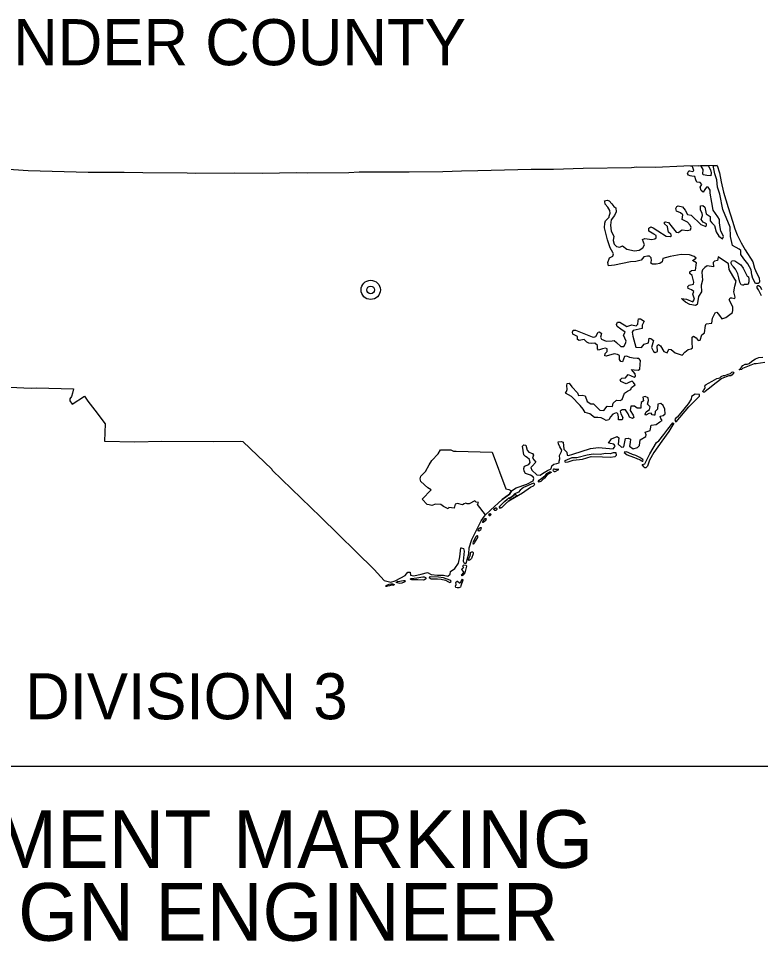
# Model space of a CAD drawing. Extents: x -63 to 3072, y 0 to 1100.
# Drawn here: x 1596 to 1653.9, y 945.4 to 1017.5 of the extents above; entities that cross this region are included whole.
import ezdxf

# ---------------------------------------------------------------- set-up
doc = ezdxf.new("R2010")
doc.units = 0
doc.layers.add('Level 15', color=7, linetype='Continuous')
doc.layers.add('Sheet_Plan_CELL', color=7, linetype='Continuous')

msp = doc.modelspace()

# ---------------------------------------------------------------- linework, layer by layer
at = {"layer": 'Level 15'}
for points in [[(1631.909, 979.673), (1631.735, 979.69), (1631.618, 979.805), (1631.178, 979.557), (1631.014, 979.558), (1630.928, 979.613), (1630.8, 979.581), (1630.649, 979.499), (1630.258, 979.606), (1630.083, 979.542), (1630.014, 979.23), (1629.599, 979.274), (1629.543, 979.189), (1629.177, 979.359), (1628.961, 979.53), (1628.554, 979.545), (1628.263, 979.446), (1628.064, 979.48), (1627.894, 979.522), (1627.502, 979.938), (1628.202, 980.67), (1627.955, 980.82), (1627.422, 981.301), (1627.363, 981.513), (1627.412, 981.721), (1627.762, 982.081), (1628.046, 982.615), (1628.254, 982.945), (1628.758, 983.482), (1628.946, 983.775), (1629.402, 983.792), (1629.758, 983.786), (1629.946, 983.686), (1630.177, 983.674), (1632.98, 983.611), (1634.041, 980.734), (1634.264, 980.682), (1634.491, 980.574), (1634.324, 980.333), (1633.758, 979.919), (1632.842, 979.08), (1632.45, 978.717), (1631.828, 979.525)], [(1634.702, 980.071), (1634.284, 979.814), (1634.023, 979.561), (1633.714, 979.272), (1633.568, 979.235), (1633.532, 979.285), (1633.547, 979.361), (1633.624, 979.445), (1633.945, 979.752), (1634.147, 979.903), (1634.17, 979.936), (1634.242, 980.01), (1634.358, 980.021), (1634.645, 980.219), (1634.729, 980.344), (1634.911, 980.192)], [(1633.123, 979.177), (1633.244, 979.256), (1633.283, 979.262), (1633.333, 979.211), (1633.341, 979.178), (1633.326, 979.13), (1633.29, 979.086), (1633.254, 979.06), (1633.224, 979.05), (1633.19, 979.046), (1633.152, 979.081), (1633.115, 979.13)], [(1632.863, 978.708), (1632.76, 978.653), (1632.722, 978.718), (1632.776, 978.778)]]:
    msp.add_lwpolyline(points, close=True, dxfattribs=at)
for radius in [0.752, 0.3]:
    msp.add_circle((1623.5, 996.27), radius, dxfattribs=at)
at = {"layer": 'Sheet_Plan_CELL'}
msp.add_line((1662.022, 959.06), (1562.024, 959.06), dxfattribs=at)
for points in [[(1650.508, 1005.987), (1647.919, 1005.917), (1645.716, 1005.833), (1644.265, 1005.84), (1643.848, 1005.793), (1640.061, 1005.739), (1637.767, 1005.667), (1636.007, 1005.661), (1631.854, 1005.569), (1630.568, 1005.527), (1629.128, 1005.496), (1626.496, 1005.468), (1625.258, 1005.452), (1622.589, 1005.446), (1621.795, 1005.395), (1618.594, 1005.382), (1617.714, 1005.41), (1615.069, 1005.352), (1612.887, 1005.382), (1609.813, 1005.346), (1609.189, 1005.384), (1605.718, 1005.394), (1604.28, 1005.421), (1601.974, 1005.443), (1601.468, 1005.431), (1596.787, 1005.562), (1594.085, 1005.742)], [(1649.267, 1004.036), (1649.193, 1004.3), (1649.328, 1004.483), (1649.191, 1004.647), (1648.941, 1004.667), (1648.853, 1004.864), (1648.779, 1005.128), (1648.556, 1005.143), (1648.42, 1005.169), (1648.292, 1005.235), (1648.218, 1005.36), (1648.298, 1005.553), (1648.399, 1005.562), (1648.614, 1005.507), (1648.703, 1005.601), (1648.62, 1005.825), (1648.557, 1005.934), (1648.429, 1005.931)], [(1649.1, 1005.948), (1649.812, 1005.966), (1649.998, 1005.652), (1650.052, 1005.412), (1650.034, 1005.171), (1649.705, 1005.205), (1649.466, 1005.251), (1649.404, 1005.306), (1649.416, 1005.663), (1649.277, 1005.919), (1649.1, 1005.948)], [(1650.508, 1005.987), (1650.701, 1005.419), (1650.819, 1004.693), (1651.009, 1003.896), (1651.383, 1002.706), (1651.722, 1001.638), (1651.905, 1001.03), (1652.087, 1000.566), (1652.385, 999.951), (1652.709, 999.402), (1653.288, 998.461), (1653.433, 997.962), (1653.589, 997.589), (1653.79, 997.222), (1653.823, 996.898), (1653.783, 996.828), (1653.704, 996.761), (1653.612, 996.758), (1653.518, 996.765), (1653.3, 997.161), (1653.225, 997.433), (1653.16, 997.83), (1652.906, 998.293), (1652.593, 998.683), (1652.358, 999.028), (1652.352, 999.357), (1652.227, 999.453), (1651.718, 999.738), (1651.552, 1000.427), (1651.538, 1001.159), (1650.972, 1002.542), (1650.718, 1003.751), (1650.534, 1004.289), (1650.504, 1004.868), (1650.331, 1005.318), (1650.2, 1005.976), (1650.508, 1005.987)], [(1642.456, 1002.782), (1642.62, 1002.682), (1642.646, 1002.374), (1642.519, 1002.079), (1642.256, 1001.727), (1642.194, 1001.324), (1642.259, 1000.856), (1642.464, 1000.46), (1642.414, 1000.125), (1642.499, 999.833), (1642.674, 999.649), (1642.917, 999.605), (1643.135, 999.716), (1643.475, 999.446), (1644.078, 999.307), (1644.441, 999.377), (1644.712, 999.547), (1644.858, 999.796), (1644.77, 999.992), (1644.687, 1000.214), (1644.869, 1000.29), (1645.413, 1000.203), (1645.647, 1000.255), (1645.76, 1000.331), (1645.767, 1000.509), (1645.59, 1000.611), (1645.191, 1000.865), (1645.191, 1001.086), (1645.336, 1001.183), (1645.534, 1001.119), (1645.896, 1000.885), (1646.545, 1000.473), (1646.858, 1000.428), (1646.96, 1000.519), (1646.911, 1000.625), (1646.729, 1000.77), (1646.681, 1001.027), (1646.647, 1001.213), (1646.423, 1001.435), (1646.403, 1001.549), (1646.481, 1001.59), (1646.72, 1001.517), (1647.004, 1001.173), (1647.334, 1000.78), (1647.509, 1000.746), (1647.649, 1000.886), (1647.789, 1000.956), (1648.186, 1000.908), (1648.435, 1000.957), (1648.485, 1001.141), (1648.424, 1001.332), (1648.215, 1001.552), (1647.778, 1001.759), (1647.849, 1002.119), (1647.669, 1002.278), (1647.36, 1002.42), (1647.288, 1002.627), (1647.376, 1002.79), (1647.481, 1002.825), (1647.82, 1002.761), (1648.022, 1002.501), (1648.195, 1002.164), (1648.49, 1002.094), (1649.246, 1001.369), (1649.636, 1001.211), (1649.7, 1001.323), (1649.681, 1001.438), (1649.44, 1001.567), (1649.268, 1001.766), (1649.388, 1002.088), (1649.35, 1002.248), (1649.213, 1002.482), (1649.225, 1002.826), (1649.414, 1002.858), (1649.556, 1002.721), (1649.664, 1002.202), (1649.986, 1001.987), (1649.964, 1001.66), (1650.102, 1001.509), (1650.3, 1001.305), (1650.44, 1000.808), (1650.636, 1000.452), (1650.947, 1000.254), (1650.955, 1000.294), (1651.025, 1000.432), (1650.954, 1000.57), (1650.799, 1000.849), (1650.758, 1001.133), (1650.689, 1001.492), (1650.701, 1001.767), (1650.56, 1001.974), (1650.214, 1002.497), (1650.106, 1003.086), (1649.971, 1003.818), (1649.975, 1004.053), (1649.825, 1004.29), (1649.684, 1004.289), (1649.565, 1004.118), (1649.439, 1003.906), (1649.267, 1004.036)], [(1648.882, 998.746), (1648.738, 998.87), (1648.371, 998.996), (1647.705, 999.026), (1646.865, 998.881), (1646.287, 998.715), (1646.221, 998.452), (1646.058, 998.331), (1645.754, 998.278), (1645.477, 998.288), (1645.352, 998.367), (1645.391, 998.566), (1645.375, 998.776), (1645.234, 998.912), (1645.08, 998.914), (1644.787, 998.844), (1644.582, 998.58), (1644.173, 998.49), (1643.748, 998.459), (1642.509, 998.192), (1642.054, 998.152), (1642.007, 998.271), (1641.991, 998.411), (1642.116, 998.774), (1642.39, 998.889), (1642.438, 999.073), (1642.391, 999.192), (1642.181, 999.561), (1641.963, 1000.18), (1641.745, 1001.103), (1641.759, 1001.473), (1641.811, 1001.67), (1641.984, 1001.846), (1642.086, 1001.938), (1642.103, 1002.031), (1642.162, 1002.269), (1642.144, 1002.466), (1641.981, 1002.717), (1641.788, 1002.96), (1641.756, 1003.159), (1641.741, 1003.231), (1641.933, 1003.279), (1642.091, 1003.222), (1642.313, 1002.988), (1642.456, 1002.782)], [(1644.672, 993.247), (1643.974, 993.089), (1643.882, 992.969), (1643.931, 992.645), (1644.17, 991.793), (1644.623, 991.764), (1644.815, 992.042), (1645.154, 992.144), (1645.209, 992.503), (1645.344, 992.478), (1645.548, 992.316), (1645.388, 991.771), (1645.564, 991.465), (1645.686, 991.374), (1645.856, 991.465), (1645.841, 991.892), (1645.945, 991.995), (1646.093, 991.899), (1646.367, 991.451), (1646.627, 991.361), (1646.737, 991.641), (1646.943, 991.629), (1647.239, 991.368), (1647.799, 991.18), (1647.985, 991.418), (1648.245, 991.615), (1648.491, 991.664), (1648.592, 991.754), (1648.576, 992.168), (1648.574, 992.579), (1648.686, 992.654), (1648.882, 992.52), (1649.036, 992.313), (1649.194, 992.338), (1649.32, 992.766), (1649.531, 992.917), (1649.603, 993.493), (1649.669, 993.617), (1650.095, 993.659), (1650.147, 994.061), (1650.357, 994.487), (1650.504, 994.527), (1650.707, 994.282), (1650.874, 994.003), (1651.187, 994.107), (1651.712, 994.5), (1651.751, 994.698), (1651.729, 994.936), (1651.449, 995.485), (1651.524, 995.649), (1651.65, 995.652), (1651.902, 995.59), (1651.924, 995.695), (1651.815, 996.129), (1651.903, 996.566), (1651.996, 996.961), (1651.902, 997.117), (1651.74, 997.355), (1651.448, 997.853), (1651.398, 998.304), (1650.609, 998.842), (1650.607, 998.829), (1650.54, 998.566), (1650.306, 998.515), (1650.215, 998.408), (1650.243, 998.058), (1649.745, 998.154), (1649.565, 998.023), (1649.372, 997.826), (1649.322, 997.643), (1649.368, 997.028), (1649.276, 996.633), (1649.286, 996.122), (1649.073, 995.75), (1648.974, 995.247), (1648.964, 995.125), (1648.836, 995.04), (1648.395, 995.138), (1648.053, 995.313), (1647.858, 995.46), (1647.734, 995.607), (1648.126, 995.546), (1648.616, 995.343), (1648.741, 995.552), (1648.624, 995.946), (1648.692, 996.153), (1648.522, 996.282), (1648.247, 996.375), (1648.222, 996.531), (1648.326, 996.635), (1648.662, 996.709), (1648.693, 996.868), (1648.572, 997.387), (1648.396, 997.558), (1648.39, 997.669), (1648.508, 997.771), (1648.839, 997.818), (1648.908, 998.383), (1648.592, 998.554), (1648.882, 998.746)], [(1651.707, 998.551), (1651.886, 998.525), (1652.126, 998.38), (1652.354, 998.235), (1652.536, 997.967), (1652.709, 997.648), (1652.861, 997.351), (1652.951, 997.296), (1652.99, 997.119), (1652.99, 996.888), (1652.93, 996.709), (1652.867, 996.684), (1652.819, 996.703), (1652.633, 996.687), (1652.577, 996.649), (1652.491, 996.636), (1652.389, 996.674), (1652.294, 996.872), (1652.212, 997.21), (1652.142, 997.523), (1651.959, 997.876), (1651.79, 998.065), (1651.698, 998.166), (1651.615, 998.341), (1651.604, 998.43), (1651.624, 998.496), (1651.7, 998.549)], [(1653.967, 995.795), (1653.748, 996.286), (1653.638, 996.432), (1653.628, 996.504), (1653.634, 996.562), (1653.684, 996.613), (1653.752, 996.616), (1653.877, 996.521), (1653.988, 996.298)], [(1640.677, 987.387), (1640.883, 987.377), (1641.371, 986.893), (1641.683, 986.863), (1641.937, 987.184), (1642.347, 987.163), (1642.41, 987.424), (1642.663, 987.663), (1642.948, 987.638), (1643.099, 987.706), (1643.293, 988.215), (1643.531, 988.375), (1643.774, 988.494), (1643.831, 988.647), (1644.122, 988.865), (1644.005, 989.051), (1643.884, 989.141), (1643.688, 989.055), (1643.417, 988.942), (1643.01, 989.126), (1642.952, 989.26), (1643.087, 989.385), (1643.38, 989.399), (1643.569, 989.664), (1644.057, 989.464), (1644.155, 989.542), (1644.118, 989.712), (1643.837, 990.051), (1644.043, 990.04), (1644.355, 990.009), (1644.48, 990.082), (1644.524, 990.456), (1644.553, 990.751), (1644.418, 990.913), (1644.281, 990.925), (1643.966, 990.943), (1643.714, 991.003), (1643.483, 991.1), (1643.296, 991.067), (1643.135, 990.659), (1643.002, 990.684), (1642.893, 990.841), (1642.894, 991.141), (1642.744, 991.223), (1642.476, 991.273), (1641.874, 991.096), (1641.769, 991.129), (1641.772, 991.293), (1641.944, 991.466), (1641.952, 991.656), (1641.798, 991.725), (1641.566, 991.672), (1641.271, 991.576), (1641.19, 991.659), (1641.186, 991.933), (1640.969, 992.109), (1640.686, 992.079), (1640.511, 992.111), (1640.344, 992.182), (1640.148, 992.395), (1639.759, 992.316), (1639.637, 992.406), (1639.639, 992.638), (1639.255, 992.817), (1639.229, 992.972), (1639.299, 993.124), (1639.467, 993.134), (1640.772, 992.61), (1640.906, 992.586), (1641.055, 992.641), (1641.227, 992.965), (1641.345, 992.998), (1641.486, 992.863), (1641.417, 992.575), (1641.5, 992.423), (1641.861, 992.274), (1642.337, 992.297), (1642.492, 992.309), (1642.657, 992.155), (1643.017, 991.857), (1643.236, 991.843), (1643.365, 992.08), (1643.429, 992.273), (1643.212, 992.737), (1643.354, 992.971), (1643.008, 993.199), (1642.716, 993.418), (1642.663, 993.578), (1642.752, 993.753), (1642.935, 993.761), (1643.478, 993.4), (1643.854, 993.55), (1644.2, 993.472), (1644.336, 993.597), (1644.357, 993.854), (1644.385, 993.999), (1644.538, 993.998), (1644.837, 993.819), (1644.666, 993.508), (1644.672, 993.247)], [(1654.225, 990.601), (1653.57, 990.51), (1653.401, 990.501), (1652.486, 990.121), (1652.416, 990.059), (1652.297, 990.019), (1652.242, 990.052), (1652.329, 990.111), (1652.392, 990.211), (1652.514, 990.379), (1652.692, 990.479), (1652.858, 990.464), (1653.005, 990.521), (1653.217, 990.693), (1653.496, 990.895), (1653.779, 990.994), (1654.075, 991.027)], [(1651.815, 989.821), (1651.778, 989.753), (1651.699, 989.642), (1651.583, 989.57), (1651.422, 989.562), (1650.89, 989.345), (1650.443, 989.026), (1649.83, 988.509), (1649.593, 988.328), (1649.519, 988.291), (1649.449, 988.299), (1649.408, 988.343), (1649.432, 988.428), (1649.504, 988.492), (1649.552, 988.561), (1649.586, 988.663), (1649.557, 988.779), (1649.589, 988.839), (1649.656, 988.884), (1649.847, 988.993), (1650.142, 989.149), (1650.494, 989.349), (1650.631, 989.37), (1650.735, 989.409), (1650.829, 989.499), (1650.879, 989.538), (1651, 989.584), (1651.108, 989.577), (1651.378, 989.68), (1651.557, 989.754), (1651.673, 989.836), (1651.732, 989.865), (1651.777, 989.855), (1651.822, 989.823)], [(1593.046, 988.785), (1597.03, 988.609), (1597.432, 988.636), (1600.317, 988.553), (1600.253, 988.197), (1600.175, 987.937), (1600.041, 987.766), (1600.047, 987.617), (1600.215, 987.35), (1601.168, 987.975), (1601.442, 987.586), (1601.973, 986.889), (1602.789, 985.802), (1602.745, 984.458), (1605.092, 984.422), (1607.203, 984.454), (1611.225, 984.44), (1613.377, 984.453), (1613.54, 984.442), (1615.797, 982.272), (1615.811, 982.189), (1619.579, 978.567), (1623.778, 974.451), (1624.539, 973.575)], [(1642.055, 984.308), (1642.271, 984.648), (1642.73, 984.822), (1642.838, 984.734), (1642.809, 984.223), (1643.067, 983.986), (1643.239, 984.022), (1643.277, 984.15), (1643.364, 984.677), (1643.573, 984.693), (1643.752, 984.619), (1643.731, 984.365), (1643.673, 984.063), (1643.978, 983.857), (1644.301, 983.96), (1644.458, 984.135), (1644.527, 984.57), (1644.96, 984.815), (1644.985, 984.947), (1644.901, 985.153), (1645.298, 985.282), (1645.31, 985.416), (1645.382, 985.715), (1645.761, 985.753), (1646.052, 985.971), (1646.223, 986.074), (1646.116, 986.231), (1646.082, 986.414), (1646.313, 986.466), (1646.474, 986.585), (1646.434, 986.947), (1646.312, 987.242), (1646.135, 987.398), (1645.89, 987.349), (1645.872, 986.971), (1645.683, 986.775), (1645.656, 986.494), (1645.584, 986.48), (1645.454, 986.518), (1645.367, 986.643), (1645.195, 986.608), (1644.951, 986.49), (1644.897, 986.568), (1644.973, 986.744), (1645.231, 986.941), (1645.283, 987.136), (1645.073, 987.339), (1645.158, 987.636), (1645.129, 987.846), (1644.899, 987.943), (1644.724, 987.894), (1644.767, 987.614), (1644.59, 987.483), (1644.555, 987.231), (1644.557, 987.026), (1644.283, 987.036), (1644.066, 987.199), (1643.787, 987.183), (1643.737, 986.852), (1643.973, 986.495), (1644.033, 986.307), (1643.922, 986.232), (1643.695, 986.343), (1643.575, 986.583), (1643.359, 986.895), (1643.1, 986.915), (1642.966, 986.791), (1643.014, 986.605), (1643.166, 986.318), (1643.115, 986.124), (1642.812, 986.125), (1642.831, 986.366), (1642.782, 986.62), (1642.654, 986.671), (1642.386, 986.571), (1642.208, 986.359), (1642.068, 986.126), (1641.851, 986.071), (1641.676, 986.171), (1641.478, 986.289), (1641.22, 986.309), (1640.957, 986.302), (1640.585, 986.601), (1640.217, 986.695), (1640.059, 986.955), (1639.825, 987.256), (1639.151, 987.936), (1638.691, 988.21), (1638.769, 988.332), (1638.827, 988.499), (1638.787, 988.805), (1638.832, 988.974), (1638.971, 988.977), (1639.194, 988.691), (1639.623, 988.246), (1639.706, 988.027), (1639.999, 988.042), (1640.224, 987.987), (1640.377, 987.551), (1640.677, 987.387)], [(1647.323, 985.961), (1648.299, 987.151), (1649.145, 987.961), (1649.146, 988.105), (1648.807, 988.129), (1648.521, 987.948), (1648.488, 987.731), (1648.264, 987.372), (1647.693, 986.673), (1647.41, 986.335), (1647.333, 986.312), (1647.219, 986.141), (1647.268, 985.985), (1647.318, 985.956)], [(1647.048, 985.898), (1647.14, 985.87), (1646.758, 985.225), (1646.205, 984.46), (1645.568, 983.588), (1645.234, 982.976), (1645.082, 982.518), (1644.944, 982.373), (1644.884, 982.391), (1644.81, 982.467), (1644.668, 982.63), (1644.874, 982.684), (1645.257, 983.47), (1645.779, 984.363), (1645.977, 984.483), (1646.364, 984.981), (1646.682, 985.393), (1647.058, 985.897)], [(1624.539, 973.575), (1625.063, 973.462), (1625.419, 973.564), (1625.85, 973.787), (1626.182, 973.987), (1626.39, 974.247), (1626.566, 974.245), (1626.605, 973.997), (1626.866, 973.94), (1627.445, 974.071), (1627.929, 974.204), (1628.202, 974.051), (1628.71, 974.005), (1629.182, 973.992), (1629.51, 973.923), (1629.686, 974.081), (1629.721, 974.276), (1630.048, 974.516), (1630.338, 974.936), (1630.454, 975.44), (1630.523, 976.141), (1630.562, 976.134), (1630.732, 976.091), (1630.79, 975.88), (1630.721, 975.099), (1630.763, 974.997), (1630.852, 974.934), (1630.94, 974.935), (1630.979, 974.991), (1631.03, 975.234), (1631.161, 975.668), (1631.191, 976.147), (1631.398, 976.784), (1631.734, 977.453), (1632.121, 978.248), (1632.363, 978.611), (1632.45, 978.717), (1632.842, 979.08), (1633.758, 979.919), (1634.324, 980.333), (1634.491, 980.574), (1634.848, 980.809), (1635.669, 981.11), (1636.182, 981.371), (1636.227, 981.539), (1636.158, 981.686), (1635.973, 981.8), (1635.573, 981.938), (1635.471, 982.132), (1635.454, 982.338), (1635.498, 982.506), (1635.837, 982.636), (1635.934, 982.795), (1635.895, 983.032), (1635.701, 983.175), (1635.58, 983.264), (1635.453, 983.395), (1635.341, 984.065), (1635.445, 984.182), (1635.605, 984.154), (1635.698, 983.758), (1635.833, 983.598), (1636.13, 983.492), (1636.204, 983.37), (1636.105, 983.13), (1636.366, 982.827), (1636.088, 982.51), (1635.985, 982.393), (1636.058, 982.191), (1636.459, 981.836), (1636.703, 981.819), (1636.889, 981.935), (1637.287, 982.162), (1637.575, 982.313), (1637.616, 982.536), (1637.778, 982.67), (1638.007, 982.724), (1638.192, 982.758), (1638.19, 982.894), (1638.253, 983.086), (1638.217, 983.336), (1638.386, 983.658), (1638.405, 983.763), (1638.258, 984.007), (1638.139, 984.259), (1638.113, 984.413), (1638.349, 984.425), (1638.519, 984.38), (1638.571, 983.842), (1638.79, 983.613), (1638.815, 983.378), (1638.919, 983.346), (1639.254, 983.448), (1640.644, 983.901), (1641.274, 983.962), (1642.397, 983.865), (1642.502, 983.981), (1642.567, 984.105), (1642.451, 984.221), (1642.055, 984.308)], [(1639.188, 983.156), (1638.637, 982.937), (1638.624, 982.871), (1638.724, 982.823), (1638.897, 982.852), (1639.3, 982.973), (1640.01, 983.051), (1640.694, 983.258), (1641.589, 983.233), (1642.168, 983.207), (1642.57, 983.262), (1642.657, 983.362), (1642.646, 983.541), (1642.409, 983.544), (1642.165, 983.461), (1641.801, 983.487), (1641.391, 983.424), (1640.851, 983.436), (1640.384, 983.359), (1639.576, 983.164), (1639.191, 983.157)], [(1643.27, 983.573), (1643.502, 983.386), (1643.99, 983.211), (1644.204, 983.137), (1644.308, 983.072), (1644.416, 983.052), (1644.512, 983.013), (1644.65, 982.935), (1644.667, 982.909), (1644.711, 982.897), (1644.748, 982.946), (1644.712, 983.025), (1644.496, 983.19), (1644.176, 983.349), (1643.926, 983.421), (1643.634, 983.546), (1643.437, 983.618), (1643.365, 983.615), (1643.304, 983.617), (1643.286, 983.609), (1643.273, 983.588), (1643.269, 983.579)], [(1637.885, 982.093), (1638.159, 982.258), (1637.886, 982.262), (1637.838, 982.287), (1637.792, 982.293), (1637.753, 982.26), (1637.716, 982.191), (1637.732, 982.137), (1637.774, 982.107), (1637.82, 982.084), (1637.882, 982.091)], [(1637.125, 981.794), (1637.241, 981.934), (1637.359, 982.024), (1637.451, 982.062), (1637.529, 982.06), (1637.575, 982.049), (1637.581, 982.02), (1637.447, 981.936), (1637.351, 981.874), (1637.187, 981.735), (1637.053, 981.585), (1636.881, 981.416), (1636.775, 981.319), (1636.694, 981.274), (1636.629, 981.265), (1636.588, 981.29), (1636.585, 981.344), (1636.631, 981.418), (1636.732, 981.505), (1637.083, 981.756), (1637.13, 981.803)], [(1633.945, 979.752), (1633.624, 979.445), (1633.547, 979.361), (1633.532, 979.285), (1633.568, 979.235), (1633.714, 979.272), (1634.023, 979.561), (1634.284, 979.814), (1634.702, 980.071), (1635.33, 980.434), (1635.972, 980.874), (1636.198, 980.965), (1636.255, 981.021), (1636.309, 981.14), (1636.188, 981.186), (1636.02, 981.096), (1635.604, 980.919), (1635.416, 980.836), (1635.156, 980.636), (1635.017, 980.483), (1634.729, 980.344), (1634.645, 980.219), (1634.358, 980.021), (1634.242, 980.01), (1634.17, 979.936), (1634.147, 979.903), (1633.959, 979.761)], [(1633.123, 979.177), (1633.244, 979.256), (1633.283, 979.262), (1633.306, 979.244), (1633.333, 979.211), (1633.341, 979.178), (1633.326, 979.13), (1633.29, 979.086), (1633.254, 979.06), (1633.224, 979.05), (1633.19, 979.046), (1633.152, 979.081), (1633.115, 979.13), (1633.109, 979.157), (1633.123, 979.177)], [(1632.776, 978.778), (1632.722, 978.718), (1632.716, 978.685), (1632.731, 978.659), (1632.76, 978.653), (1632.807, 978.666), (1632.863, 978.708), (1632.884, 978.734), (1632.877, 978.758), (1632.83, 978.8), (1632.814, 978.806), (1632.792, 978.797), (1632.78, 978.783)], [(1632.238, 978.183), (1632.312, 978.307), (1632.39, 978.391), (1632.437, 978.426), (1632.473, 978.429), (1632.503, 978.402), (1632.521, 978.364), (1632.482, 978.32), (1632.415, 978.23), (1632.356, 978.171), (1632.267, 978.123), (1632.241, 978.122), (1632.223, 978.135), (1632.215, 978.15), (1632.238, 978.183)], [(1631.478, 976.538), (1631.469, 976.451), (1631.484, 976.444), (1631.519, 976.449), (1631.569, 976.477), (1631.599, 976.516), (1631.856, 976.947), (1631.865, 977.004), (1631.855, 977.034), (1631.817, 977.06), (1631.78, 977.06), (1631.726, 977.029), (1631.694, 976.989), (1631.495, 976.599), (1631.477, 976.539)], [(1631.873, 977.484), (1631.914, 977.575), (1631.966, 977.65), (1632.015, 977.689), (1632.074, 977.72), (1632.108, 977.711), (1632.121, 977.68), (1632.099, 977.61), (1632.061, 977.525), (1632.02, 977.485), (1631.965, 977.449), (1631.893, 977.456), (1631.875, 977.464), (1631.872, 977.491)], [(1631.269, 975.546), (1631.275, 975.669), (1631.284, 975.76), (1631.326, 975.806), (1631.386, 975.832), (1631.445, 975.815), (1631.503, 975.77), (1631.502, 975.657), (1631.348, 975.292), (1631.261, 975.188), (1631.183, 975.149), (1631.135, 975.171), (1631.129, 975.231), (1631.191, 975.363), (1631.271, 975.553)], [(1630.734, 974.615), (1630.684, 974.532), (1630.601, 974.474), (1630.589, 974.449), (1630.594, 974.416), (1630.683, 974.323), (1630.73, 974.284), (1630.749, 974.269), (1630.748, 974.219), (1630.57, 974.033), (1630.555, 974.006), (1630.608, 973.964), (1630.644, 973.976), (1630.727, 974.027), (1630.862, 974.187), (1631.009, 974.693)], [(1631.009, 974.693), (1630.935, 974.765), (1630.761, 974.79), (1630.703, 974.755), (1630.664, 974.721), (1630.674, 974.686), (1630.734, 974.615)], [(1625.62, 973.518), (1626.051, 973.574), (1626.136, 973.573), (1626.177, 973.558), (1626.163, 973.492), (1626.103, 973.444), (1625.92, 973.371), (1625.779, 973.351), (1625.556, 973.407), (1625.498, 973.436), (1625.535, 973.485), (1625.63, 973.526)], [(1626.668, 973.754), (1627.088, 973.787), (1627.553, 973.866), (1627.669, 973.873), (1627.766, 973.821), (1627.819, 973.756), (1627.807, 973.713), (1627.697, 973.633), (1627.614, 973.61), (1627.163, 973.634), (1626.838, 973.643), (1626.704, 973.644), (1626.631, 973.666), (1626.603, 973.69), (1626.603, 973.708), (1626.607, 973.723), (1626.666, 973.749)], [(1628.049, 973.824), (1628.212, 973.72), (1628.383, 973.727), (1628.706, 973.716), (1628.998, 973.684), (1629.327, 973.613), (1629.57, 973.485), (1629.672, 973.441), (1629.762, 973.482), (1629.741, 973.568), (1629.67, 973.617), (1629.179, 973.782), (1628.785, 973.858), (1628.139, 973.865), (1628.049, 973.854), (1628.054, 973.824)], [(1630.256, 973.521), (1630.418, 973.407), (1630.459, 973.393), (1630.518, 973.464), (1630.597, 973.657), (1630.642, 973.677), (1630.678, 973.617), (1630.527, 973.177), (1630.493, 973.07), (1630.363, 973.008), (1630.252, 973.002), (1630.151, 973.041), (1630.119, 973.141), (1630.158, 973.263), (1630.146, 973.434), (1630.16, 973.47), (1630.245, 973.526), (1630.271, 973.521)], [(1624.681, 973.159), (1624.769, 973.218), (1624.946, 973.291), (1625.066, 973.321), (1625.143, 973.327), (1625.209, 973.319), (1625.283, 973.299), (1625.318, 973.284), (1625.327, 973.265), (1625.32, 973.251), (1625.235, 973.205), (1625.215, 973.212), (1625.197, 973.227), (1625.118, 973.211), (1624.956, 973.18), (1624.818, 973.143), (1624.737, 973.122), (1624.707, 973.119), (1624.689, 973.137), (1624.681, 973.159)]]:
    msp.add_lwpolyline(points, dxfattribs=at)

# ---------------------------------------------------------------- texts
for s, height, p in [('PENDER COUNTY', 3.6, (1589.196, 1013.803)), ('DIVISION 3', 3.6, (1596.555, 962.752)), ('PAVEMENT MARKING', 4.5, (1577.974, 951.156)), ('DESIGN ENGINEER', 4.5, (1581.957, 945.468))]:
    msp.add_text(s, height=height, rotation=0, dxfattribs=at).set_placement(p)

doc.saveas('drawing.dxf')
